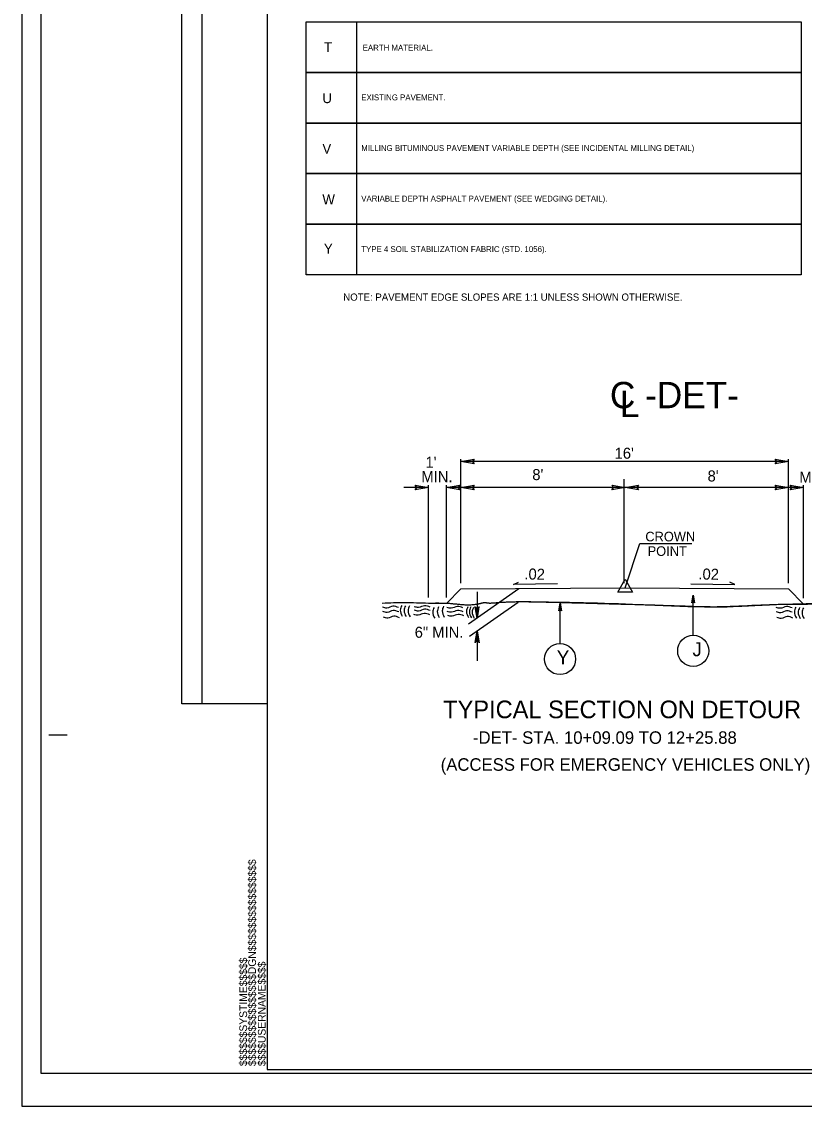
# Model space of a CAD drawing. Extents: x 575722 to 576066, y -53107 to -52774.
# Drawn here: x 575796.6 to 575849.8, y -52908.8 to -52835 of the extents above; entities that cross this region are included whole.
import ezdxf

# ---------------------------------------------------------------- set-up
doc = ezdxf.new("R2010")
doc.units = 0
for name, color, linetype in [('Old_Level_1', 7, 'Continuous'), ('Old_Level_11', 7, 'Continuous'), ('Old_Level_2', 7, 'Continuous'), ('Prop DSN Text', 7, 'Continuous'), ('Prop Pavement Schedule Description CELL', 7, 'Continuous'), ('Prop ROW Marker CELL', 7, 'Continuous'), ('Sheet Block Revision CELL', 7, 'Continuous'), ('Sheet Cutting Line CELL', 7, 'Continuous'), ('Sheet Plot Border Inside CELL', 7, 'Continuous'), ('Sheet Plot Border Outside CELL', 7, 'Continuous'), ('Sheet Typical CELL', 7, 'Continuous'), ('Typical Grade Point Symbol CELL', 7, 'Continuous'), ('Typical ID Circle CELL', 7, 'Continuous'), ('Typical Pavement Slope CELL', 7, 'Continuous'), ('Typical Terminator CELL', 7, 'Continuous'), ('Typical Text Grade Point CELL', 7, 'Continuous'), ('Typical Text ID Circle CELL', 7, 'Continuous')]:
    doc.layers.add(name, color=color, linetype=linetype)

# ---------------------------------------------------------------- blocks, each defined once
blk = doc.blocks.new('Note Standard Slope')
at = {"layer": 'Prop Pavement Schedule Description CELL'}
blk.add_line((0, 0), (0, 0), dxfattribs=at)
blk.add_text('NOTE: PAVEMENT EDGE SLOPES ARE 1:1 UNLESS SHOWN OTHERWISE.', height=5.4417, dxfattribs=at).set_placement((27.18, -20.66))

msp = doc.modelspace()

# ---------------------------------------------------------------- linework, layer by layer
at = {"layer": 'Old_Level_11'}
for p, q in [((575826.452, -52873.186), (575826.452, -52864.771)), ((575848.725, -52864.931), (575826.452, -52864.931)), ((575848.725, -52873.186), (575848.725, -52864.771)), ((575824.238, -52874.168), (575824.238, -52866.528)), ((575825.467, -52874.175), (575825.467, -52866.528)), ((575837.551, -52873.186), (575837.551, -52866.115)), ((575849.749, -52874.214), (575849.749, -52866.528)), ((575824.238, -52866.688), (575822.573, -52866.688)), ((575826.452, -52866.688), (575825.467, -52866.688)), ((575837.551, -52866.688), (575826.452, -52866.688)), ((575848.725, -52866.688), (575837.551, -52866.688)), ((575849.749, -52866.688), (575848.725, -52866.688))]:
    msp.add_line(p, q, dxfattribs=at)
for points in [[(575827.352, -52865.086), (575826.452, -52864.931), (575827.357, -52864.771), (575827.242, -52864.931)], [(575847.825, -52864.776), (575848.725, -52864.931), (575847.82, -52865.091), (575847.935, -52864.931)], [(575823.338, -52866.533), (575824.238, -52866.688), (575823.333, -52866.848), (575823.448, -52866.688)], [(575826.367, -52866.843), (575825.467, -52866.688), (575826.372, -52866.528), (575826.257, -52866.688)], [(575827.352, -52866.843), (575826.452, -52866.688), (575827.357, -52866.528), (575827.242, -52866.688)], [(575836.726, -52866.533), (575837.626, -52866.688), (575836.721, -52866.848), (575836.836, -52866.688)], [(575838.526, -52866.843), (575837.626, -52866.688), (575838.531, -52866.528), (575838.416, -52866.688)], [(575847.825, -52866.533), (575848.725, -52866.688), (575847.82, -52866.848), (575847.935, -52866.688)], [(575848.849, -52866.533), (575849.749, -52866.688), (575848.844, -52866.848), (575848.959, -52866.688)]]:
    msp.add_lwpolyline(points, close=True, dxfattribs=at)
at = {"layer": 'Old_Level_2'}
for points in [[(575854.306, -52874.519), (575853.897, -52874.539), (575852.826, -52874.492), (575851.72, -52874.564), (575848.318, -52874.649), (575843.579, -52874.817), (575839.074, -52874.683), (575831.444, -52874.481), (575829.964, -52874.479), (575829.207, -52874.512), (575828.471, -52874.567), (575828.361, -52874.564), (575828.252, -52874.549), (575828.142, -52874.535), (575828.032, -52874.534), (575827.911, -52874.553), (575827.79, -52874.581), (575827.67, -52874.611), (575827.549, -52874.633), (575826.994, -52874.688), (575826.874, -52874.688), (575826.454, -52874.659), (575826.035, -52874.619), (575825.194, -52874.568), (575824.238, -52874.568), (575822.632, -52874.522), (575821.097, -52874.576)], [(575822.422, -52874.703), (575822.328, -52875.025), (575822.462, -52875.442)], [(575822.213, -52874.857), (575821.823, -52874.763), (575821.42, -52874.884), (575821.124, -52874.83)], [(575822.227, -52875.153), (575821.837, -52875.059), (575821.434, -52875.18), (575821.138, -52875.126)], [(575822.267, -52875.543), (575821.877, -52875.449), (575821.474, -52875.57), (575821.178, -52875.516)], [(575822.677, -52874.729), (575822.583, -52875.052), (575822.717, -52875.469)], [(575822.946, -52874.743), (575822.852, -52875.065), (575822.986, -52875.482)], [(575824.337, -52875.345), (575823.947, -52875.251), (575823.544, -52875.372), (575823.248, -52875.318)], [(575824.364, -52874.821), (575823.974, -52874.727), (575823.571, -52874.848), (575823.275, -52874.794)], [(575824.364, -52875.063), (575823.974, -52874.969), (575823.571, -52875.09), (575823.275, -52875.036)], [(575824.624, -52874.841), (575824.53, -52875.164), (575824.665, -52875.58)], [(575824.934, -52874.801), (575824.84, -52875.123), (575824.974, -52875.54)], [(575825.27, -52874.76), (575825.176, -52875.083), (575825.31, -52875.5)], [(575826.589, -52874.876), (575826.199, -52874.782), (575825.796, -52874.903), (575825.5, -52874.849)], [(575826.602, -52875.145), (575826.212, -52875.051), (575825.809, -52875.172), (575825.514, -52875.118)], [(575826.643, -52875.413), (575826.253, -52875.319), (575825.85, -52875.44), (575825.554, -52875.387)], [(575826.919, -52874.8), (575826.824, -52875.123), (575826.959, -52875.54)], [(575827.12, -52874.814), (575827.026, -52875.136), (575827.16, -52875.553)], [(575827.308, -52874.841), (575827.214, -52875.163), (575827.349, -52875.58)], [(575848.976, -52874.879), (575848.586, -52874.785), (575848.183, -52874.906), (575847.887, -52874.852)], [(575848.989, -52875.175), (575848.599, -52875.081), (575848.196, -52875.202), (575847.9, -52875.148)], [(575849.222, -52874.825), (575849.128, -52875.147), (575849.262, -52875.564)], [(575849.477, -52874.852), (575849.383, -52875.174), (575849.517, -52875.591)], [(575849.746, -52874.865), (575849.652, -52875.188), (575849.786, -52875.604)], [(575849.029, -52875.565), (575848.64, -52875.471), (575848.236, -52875.591), (575847.941, -52875.538)]]:
    msp.add_spline(points, degree=3, dxfattribs=at)
at = {"layer": 'Prop DSN Text'}
for p, q in [((575830.393, -52873.585), (575826.974, -52875.98)), ((575827.547, -52873.784), (575827.547, -52875.579)), ((575830.341, -52874.502), (575827.039, -52876.814)), ((575827.547, -52875.579), (575827.408, -52874.792)), ((575827.547, -52875.579), (575827.428, -52874.807)), ((575827.448, -52874.821), (575827.547, -52875.579)), ((575827.547, -52875.579), (575827.467, -52874.835)), ((575827.488, -52874.85), (575827.547, -52875.579)), ((575827.547, -52875.579), (575827.508, -52874.865)), ((575827.527, -52874.879), (575827.547, -52875.579)), ((575827.547, -52875.579), (575827.687, -52874.792)), ((575827.667, -52874.807), (575827.547, -52875.579)), ((575827.547, -52875.579), (575827.645, -52874.821)), ((575827.626, -52874.835), (575827.547, -52875.579)), ((575827.547, -52875.579), (575827.606, -52874.85)), ((575827.586, -52874.865), (575827.547, -52875.579)), ((575827.547, -52875.579), (575827.567, -52874.879)), ((575827.547, -52874.894), (575827.547, -52875.579)), ((575827.547, -52876.458), (575827.408, -52877.246)), ((575827.428, -52877.231), (575827.547, -52876.458)), ((575827.547, -52876.458), (575827.448, -52877.217)), ((575827.467, -52877.201), (575827.547, -52876.458)), ((575827.547, -52876.458), (575827.488, -52877.187)), ((575827.508, -52877.173), (575827.547, -52876.458)), ((575827.547, -52876.458), (575827.527, -52877.159)), ((575827.547, -52876.458), (575827.547, -52878.48)), ((575827.547, -52876.458), (575827.687, -52877.246)), ((575827.547, -52877.144), (575827.547, -52876.458)), ((575827.567, -52877.159), (575827.547, -52876.458)), ((575827.547, -52876.458), (575827.586, -52877.173)), ((575827.606, -52877.187), (575827.547, -52876.458)), ((575827.547, -52876.458), (575827.626, -52877.201)), ((575827.645, -52877.217), (575827.547, -52876.458)), ((575827.547, -52876.458), (575827.667, -52877.231))]:
    msp.add_line(p, q, dxfattribs=at)
msp.add_open_spline([(575850.978, -52874.583), (575850.091, -52874.605), (575849.205, -52874.627), (575848.318, -52874.649), (575847.923, -52874.659), (575847.528, -52874.678), (575847.133, -52874.695), (575846.738, -52874.712), (575846.343, -52874.738), (575845.948, -52874.756), (575845.158, -52874.793), (575844.368, -52874.83), (575843.579, -52874.817), (575842.828, -52874.806), (575842.077, -52874.782), (575841.327, -52874.758), (575840.576, -52874.733), (575839.825, -52874.704), (575839.074, -52874.683), (575837.803, -52874.647), (575836.531, -52874.614), (575835.259, -52874.579), (575833.988, -52874.545), (575832.716, -52874.513), (575831.444, -52874.481), (575830.951, -52874.469), (575830.457, -52874.47), (575829.964, -52874.479), (575829.711, -52874.484), (575829.459, -52874.499), (575829.207, -52874.512), (575828.961, -52874.525), (575828.716, -52874.555), (575828.471, -52874.567), (575828.435, -52874.569), (575828.398, -52874.568), (575828.361, -52874.564), (575828.325, -52874.559), (575828.288, -52874.554), (575828.252, -52874.549), (575828.215, -52874.544), (575828.179, -52874.539), (575828.142, -52874.535), (575828.106, -52874.53), (575828.069, -52874.531), (575828.032, -52874.534), (575827.991, -52874.538), (575827.951, -52874.543), (575827.911, -52874.553), (575827.87, -52874.562), (575827.83, -52874.571), (575827.79, -52874.581), (575827.75, -52874.591), (575827.711, -52874.601), (575827.67, -52874.611), (575827.631, -52874.62), (575827.59, -52874.627), (575827.549, -52874.633), (575827.365, -52874.661), (575827.18, -52874.68), (575826.994, -52874.688), (575826.954, -52874.69), (575826.914, -52874.69), (575826.874, -52874.688), (575826.734, -52874.681), (575826.594, -52874.672), (575826.454, -52874.659), (575826.314, -52874.647), (575826.175, -52874.631), (575826.035, -52874.619), (575825.755, -52874.596), (575825.475, -52874.568), (575825.194, -52874.568), (575824.876, -52874.568), (575824.557, -52874.568), (575824.238, -52874.568)], degree=3, dxfattribs=at)
at = {"layer": 'Prop Pavement Schedule Description CELL'}
for points in [[(575819.376, -52838.469), (575815.934, -52838.469), (575815.934, -52835.026), (575849.594, -52835.026), (575849.594, -52838.469), (575819.376, -52838.469), (575819.376, -52835.026)], [(575819.376, -52841.911), (575815.934, -52841.911), (575815.934, -52838.469), (575849.594, -52838.469), (575849.594, -52841.911), (575819.376, -52841.911), (575819.376, -52838.469)], [(575819.376, -52845.354), (575815.934, -52845.354), (575815.934, -52841.911), (575849.594, -52841.911), (575849.594, -52845.354), (575819.376, -52845.354), (575819.376, -52841.911)], [(575819.376, -52848.796), (575815.934, -52848.796), (575815.934, -52845.354), (575849.594, -52845.354), (575849.594, -52848.796), (575819.376, -52848.796), (575819.376, -52845.354)], [(575819.376, -52852.239), (575815.934, -52852.239), (575815.934, -52848.796), (575849.594, -52848.796), (575849.594, -52852.239), (575819.376, -52852.239), (575819.376, -52848.796)]]:
    msp.add_lwpolyline(points, dxfattribs=at)
at = {"layer": 'Prop ROW Marker CELL'}
msp.add_line((575837.626, -52873.51), (575837.626, -52873.51), dxfattribs=at)
msp.add_lwpolyline([(575837.126, -52873.798), (575837.626, -52872.934), (575838.126, -52873.798)], close=True, dxfattribs=at)
at = {"layer": 'Sheet Block Revision CELL'}
msp.add_line((575808.859, -52881.41), (575808.859, -52805.507), dxfattribs=at)
msp.add_lwpolyline([(575807.462, -52881.41), (575807.462, -52805.507), (575813.275, -52805.507), (575813.275, -52881.41)], close=True, dxfattribs=at)
at = {"layer": 'Sheet Cutting Line CELL'}
for p, q in [((575796.575, -52798.762), (575796.575, -52908.762)), ((575796.575, -52908.762), (575964.975, -52908.762))]:
    msp.add_line(p, q, dxfattribs=at)
at = {"layer": 'Sheet Plot Border Inside CELL'}
msp.add_lwpolyline([(575964.525, -52801.007), (575797.875, -52801.007), (575797.875, -52906.517), (575964.525, -52906.517)], close=True, dxfattribs=at)
at = {"layer": 'Sheet Plot Border Outside CELL'}
msp.add_lwpolyline([(575964.975, -52798.762), (575796.575, -52798.762), (575796.575, -52908.762), (575964.975, -52908.762)], close=True, dxfattribs=at)
at = {"layer": 'Sheet Typical CELL'}
for p, q in [((575798.425, -52883.512), (575799.675, -52883.512)), ((575813.275, -52906.262), (575813.275, -52906.262)), ((575813.275, -52906.262), (575813.275, -52906.262)), ((575813.275, -52906.262), (575813.275, -52906.262)), ((575813.275, -52906.262), (575813.275, -52906.262)), ((575813.275, -52906.262), (575813.275, -52906.262)), ((575813.275, -52906.262), (575813.275, -52906.262))]:
    msp.add_line(p, q, dxfattribs=at)
msp.add_lwpolyline([(575963.275, -52801.262), (575813.275, -52801.262), (575813.275, -52906.262), (575963.275, -52906.262)], close=True, dxfattribs=at)
msp.add_lwpolyline([(575817.025, -52906.262), (575817.025, -52906.262)], dxfattribs=at)
at = {"layer": 'Typical Grade Point Symbol CELL'}
msp.add_line((575837.626, -52873.51), (575838.626, -52870.51), dxfattribs=at)
at = {"layer": 'Typical ID Circle CELL'}
for p, q in [((575833.188, -52877.297), (575833.188, -52874.563)), ((575842.249, -52876.741), (575842.249, -52874.007))]:
    msp.add_line(p, q, dxfattribs=at)
for centre in [(575842.249, -52877.799), (575833.188, -52878.355)]:
    msp.add_circle(centre, 1.058, dxfattribs=at)
at = {"layer": 'Typical Pavement Slope CELL'}
for p, q in [((575830.028, -52873.295), (575830.361, -52873.128)), ((575833.028, -52873.233), (575830.028, -52873.295)), ((575842.075, -52873.232), (575845.075, -52873.294)), ((575845.075, -52873.294), (575844.742, -52873.128)), ((575826.452, -52873.59), (575825.467, -52874.575)), ((575848.725, -52873.59), (575849.749, -52874.614))]:
    msp.add_line(p, q, dxfattribs=at)
msp.add_lwpolyline([(575826.452, -52873.59), (575837.626, -52873.51), (575848.725, -52873.59)], dxfattribs=at)
at = {"layer": 'Typical Terminator CELL'}
for points in [[(575833.099, -52875.079), (575833.188, -52874.563), (575833.28, -52875.081), (575833.188, -52875.016)], [(575842.16, -52874.523), (575842.249, -52874.007), (575842.34, -52874.526), (575842.249, -52874.46)]]:
    msp.add_lwpolyline(points, close=True, dxfattribs=at)
at = {"layer": 'Typical Text Grade Point CELL'}
msp.add_line((575838.626, -52870.51), (575842.164, -52870.51), dxfattribs=at)

# ---------------------------------------------------------------- block references
at = {"layer": 'Prop DSN Text', "xscale": 0.09000000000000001, "yscale": 0.09000000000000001}
msp.add_blockref('Note Standard Slope', (575815.999, -52852.132), dxfattribs=at)

# ---------------------------------------------------------------- texts
at = {"layer": 'Old_Level_1'}
for p in [(575830.762, -52872.94), (575842.598, -52872.942)]:
    msp.add_text('.02', height=0.75, rotation=358.80838, dxfattribs=at).set_placement(p)
at = {"layer": 'Old_Level_11'}
for s, p in [("16'", (575836.904, -52864.736)), (" 1'", (575823.76, -52865.348)), ('MIN.', (575823.76, -52866.331)), ("8'", (575831.304, -52866.19)), ("8'", (575843.225, -52866.282)), ('MIN.', (575849.467, -52866.367))]:
    msp.add_text(s, height=0.75, rotation=359.99996, dxfattribs=at).set_placement(p)
at = {"layer": 'Prop DSN Text'}
for s, height, p in [('C -DET-', 1.7897, (575836.583, -52861.302)), ('L', 1.79, (575837.26, -52861.908)), ('6" MIN.', 0.75, (575823.306, -52876.907)), ('-DET- STA. 10+09.09 TO 12+25.88', 0.85, (575827.268, -52884.118)), ('(ACCESS FOR EMERGENCY VEHICLES ONLY)', 0.85, (575825.073, -52885.949))]:
    msp.add_text(s, height=height, dxfattribs=at).set_placement(p)
at = {"layer": 'Prop Pavement Schedule Description CELL'}
for s, height, p in [('T ', 0.6732, (575817.14, -52837.091)), ('EARTH MATERIAL.', 0.3995, (575819.767, -52836.992)), ('U ', 0.6732, (575817.028, -52840.558)), ('EXISTING PAVEMENT.', 0.3995, (575819.67, -52840.37)), ('V ', 0.6732, (575817.028, -52844)), ('MILLING BITUMINOUS PAVEMENT VARIABLE DEPTH (SEE INCIDENTAL MILLING DETAIL)', 0.3995, (575819.67, -52843.813)), ('W ', 0.6732, (575817.028, -52847.443)), ('VARIABLE DEPTH ASPHALT PAVEMENT (SEE WEDGING DETAIL).', 0.3995, (575819.67, -52847.249)), ('Y', 0.673, (575817.13, -52850.789)), ('TYPE 4 SOIL STABILIZATION FABRIC (STD. 1056).', 0.3995, (575819.67, -52850.683))]:
    msp.add_text(s, height=height, dxfattribs=at).set_placement(p)
at = {"layer": 'Sheet Typical CELL'}
for s, p in [('$$$$$$$$$$$$$$$$DGN$$$$$$$$$$$$$$$$', (575812.51, -52906.026)), ('$$$$$$SYSTIME$$$$$', (575811.905, -52906.026)), ('$$$$USERNAME$$$$', (575813.167, -52906.025))]:
    msp.add_text(s, height=0.525, rotation=90, dxfattribs=at).set_placement(p)
at = {"layer": 'Typical Pavement Slope CELL'}
msp.add_text('TYPICAL SECTION ON DETOUR', height=1.2, dxfattribs=at).set_placement((575825.243, -52882.377))
at = {"layer": 'Typical Text Grade Point CELL'}
for s, p in [('CROWN', (575838.99, -52870.354)), ('POINT', (575839.147, -52871.342))]:
    msp.add_text(s, height=0.6525, dxfattribs=at).set_placement(p)
at = {"layer": 'Typical Text ID Circle CELL'}
for s, height, p in [('J ', 0.9469, (575842.197, -52878.162)), ('Y', 0.947, (575832.971, -52878.717))]:
    msp.add_text(s, height=height, dxfattribs=at).set_placement(p)

doc.saveas('drawing.dxf')
